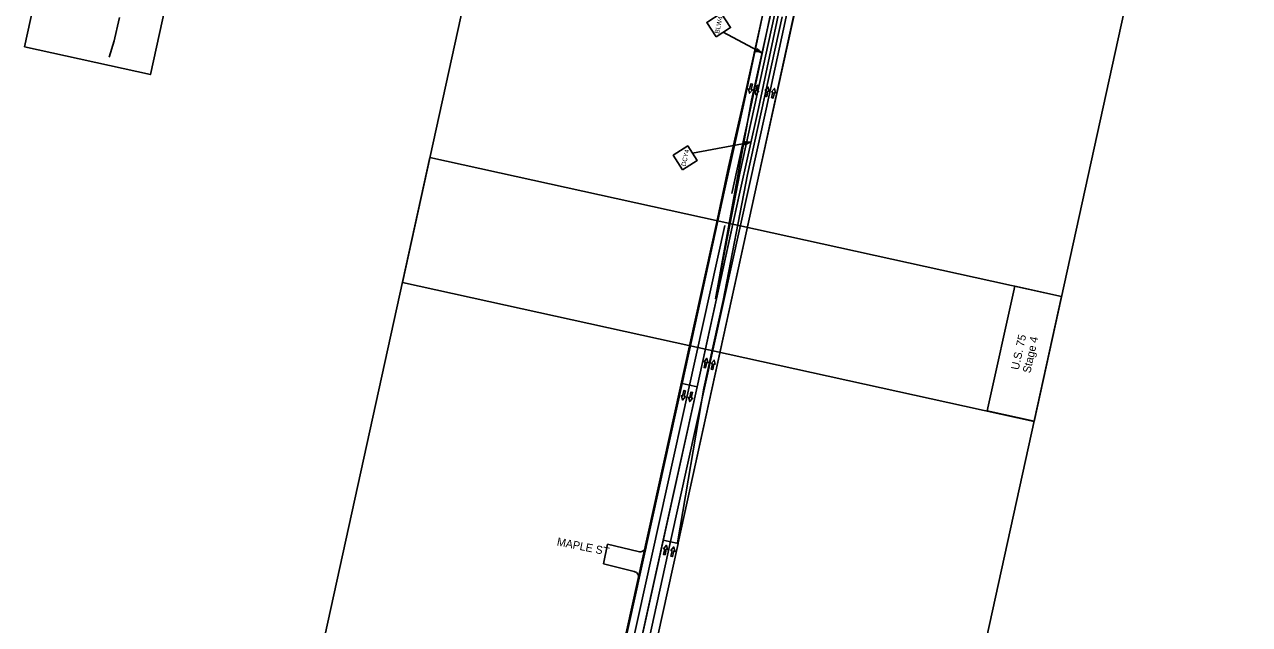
# Model space of a CAD drawing. Extents: x 14104283 to 14120882, y 8635219 to 8671666.
# Drawn here: x 14106628 to 14108541, y 8638109 to 8639045 of the extents above; entities that cross this region are included whole.
import ezdxf

# ---------------------------------------------------------------- set-up
doc = ezdxf.new("R2010")
doc.units = 0
for name, color, linetype in [('Cell', 7, 'Continuous'), ('dsnNonPlotable', 7, 'Continuous'), ('dsnPaintExistingBrokenLaneLineWhite', 7, 'Continuous'), ('dsnPaintExistingDoubleCenterLineYellow', 7, 'Continuous'), ('dsnPaintExistingDoubleCenterYellow', 7, 'Continuous'), ('dsnPaintExistingEdgeLineRightWhite', 7, 'Continuous'), ('dsnPaintPlaceBrokenLaneWhite', 7, 'Continuous'), ('dsnPaintPlaceDoubleCenterLineYellow', 7, 'Continuous'), ('dsnPaintPlaceEdgeLineRightWhite', 7, 'Continuous'), ('dsnPaintRemoveDoubleCenterLineYellow', 7, 'Continuous'), ('dsnPaintRemoveEdgeLineWhite', 7, 'Continuous'), ('dsnPaintRemoveEdgeLineYellow', 7, 'Continuous'), ('dsnShadingPaved', 7, 'Continuous'), ('dsnStdLabel', 7, 'Continuous'), ('dsnTapeRemoveChannelizingWhite', 7, 'Continuous'), ('dsnTapeRemoveChannelizingYellow', 7, 'Continuous'), ('dsnTextFinalPlan', 7, 'Continuous'), ('dsnTextOverlapEven', 7, 'Continuous'), ('dsnTextOverlapOdd', 7, 'Continuous'), ('Terrain', 7, 'Continuous')]:
    doc.layers.add(name, color=color, linetype=linetype)

msp = doc.modelspace()

# ---------------------------------------------------------------- linework, layer by layer
at = {"layer": 'Cell'}
for points in [[(14107762.5, 8638952.7), (14107764.9, 8638952.2), (14107763.1, 8638943.7), (14107764.9, 8638943.3), (14107760.5, 8638937.8), (14107758.8, 8638944.6), (14107760.6, 8638944.2)], [(14107772.5, 8638950.2), (14107774.9, 8638949.6), (14107773.1, 8638941.1), (14107774.9, 8638940.7), (14107770.5, 8638935.2), (14107768.8, 8638942), (14107770.6, 8638941.6)], [(14107787.3, 8638932.7), (14107784.8, 8638933.2), (14107786.7, 8638941.8), (14107784.9, 8638942.2), (14107789.3, 8638947.6), (14107791, 8638940.8), (14107789.2, 8638941.2)], [(14107797.4, 8638930.4), (14107795, 8638931), (14107796.8, 8638939.5), (14107795, 8638939.9), (14107799.4, 8638945.3), (14107801.1, 8638938.6), (14107799.3, 8638939)], [(14107691.9, 8638509.4), (14107689.4, 8638509.9), (14107691.3, 8638518.4), (14107689.5, 8638518.8), (14107693.9, 8638524.3), (14107695.6, 8638517.5), (14107693.7, 8638517.9)], [(14107703, 8638506.7), (14107700.6, 8638507.3), (14107702.5, 8638515.8), (14107700.6, 8638516.2), (14107705, 8638521.6), (14107706.7, 8638514.9), (14107704.9, 8638515.3)], [(14107657.9, 8638474.1), (14107660.4, 8638473.5), (14107658.5, 8638465), (14107660.3, 8638464.6), (14107655.9, 8638459.1), (14107654.2, 8638465.9), (14107656, 8638465.5)], [(14107669, 8638471.6), (14107671.4, 8638471.1), (14107669.5, 8638462.5), (14107671.4, 8638462.1), (14107667, 8638456.7), (14107665.3, 8638463.5), (14107667.1, 8638463.1)], [(14107628.6, 8638217.8), (14107626.1, 8638218.3), (14107628, 8638226.8), (14107626.2, 8638227.2), (14107630.6, 8638232.7), (14107632.3, 8638225.9), (14107630.4, 8638226.3)], [(14107640.2, 8638214.9), (14107637.8, 8638215.5), (14107639.6, 8638224), (14107637.8, 8638224.4), (14107642.2, 8638229.9), (14107643.9, 8638223.1), (14107642.1, 8638223.5)]]:
    msp.add_lwpolyline(points, close=True, dxfattribs=at)
for points in [[(14107760.6, 8638944.2), (14107758.8, 8638944.6), (14107760.5, 8638937.8), (14107764.9, 8638943.3), (14107763.1, 8638943.7), (14107764.9, 8638952.2), (14107762.5, 8638952.7), (14107760.6, 8638944.2)], [(14107770.6, 8638941.6), (14107768.8, 8638942), (14107770.5, 8638935.2), (14107774.9, 8638940.7), (14107773.1, 8638941.1), (14107774.9, 8638949.6), (14107772.5, 8638950.2), (14107770.6, 8638941.6)], [(14107789.2, 8638941.2), (14107791, 8638940.8), (14107789.3, 8638947.6), (14107784.9, 8638942.2), (14107786.7, 8638941.8), (14107784.8, 8638933.2), (14107787.3, 8638932.7), (14107789.2, 8638941.2)], [(14107799.3, 8638939), (14107801.1, 8638938.6), (14107799.4, 8638945.3), (14107795, 8638939.9), (14107796.8, 8638939.5), (14107795, 8638931), (14107797.4, 8638930.4), (14107799.3, 8638939)], [(14107693.7, 8638517.9), (14107695.6, 8638517.5), (14107693.9, 8638524.3), (14107689.5, 8638518.8), (14107691.3, 8638518.4), (14107689.4, 8638509.9), (14107691.9, 8638509.4), (14107693.7, 8638517.9)], [(14107704.9, 8638515.3), (14107706.7, 8638514.9), (14107705, 8638521.6), (14107700.6, 8638516.2), (14107702.5, 8638515.8), (14107700.6, 8638507.3), (14107703, 8638506.7), (14107704.9, 8638515.3)], [(14107656, 8638465.5), (14107654.2, 8638465.9), (14107655.9, 8638459.1), (14107660.3, 8638464.6), (14107658.5, 8638465), (14107660.4, 8638473.5), (14107657.9, 8638474.1), (14107656, 8638465.5)], [(14107667.1, 8638463.1), (14107665.3, 8638463.5), (14107667, 8638456.7), (14107671.4, 8638462.1), (14107669.5, 8638462.5), (14107671.4, 8638471.1), (14107669, 8638471.6), (14107667.1, 8638463.1)], [(14107630.4, 8638226.3), (14107632.3, 8638225.9), (14107630.6, 8638232.7), (14107626.2, 8638227.2), (14107628, 8638226.8), (14107626.1, 8638218.3), (14107628.6, 8638217.8), (14107630.4, 8638226.3)], [(14107642.1, 8638223.5), (14107643.9, 8638223.1), (14107642.2, 8638229.9), (14107637.8, 8638224.4), (14107639.6, 8638224), (14107637.8, 8638215.5), (14107640.2, 8638214.9), (14107642.1, 8638223.5)]]:
    msp.add_lwpolyline(points, dxfattribs=at)
at = {"layer": 'dsnNonPlotable'}
for points in [[(14107218.4, 8638642.3), (14107554.8, 8640173.3), (14108541.3, 8639956.6), (14108204.9, 8638425.6)], [(14106925, 8637306.7), (14107261.4, 8638837.7), (14108247.8, 8638620.9), (14107911.4, 8637089.9)]]:
    msp.add_lwpolyline(points, close=True, dxfattribs=at)
at = {"layer": 'dsnPaintExistingBrokenLaneLineWhite'}
for p, q in [((14107637.1, 8638238.2), (14107786.4, 8638912.8)), ((14107381.2, 8637189.3), (14107721.8, 8638731.5)), ((14107447.5, 8637375), (14107637.1, 8638238.2))]:
    msp.add_line(p, q, dxfattribs=at)
at = {"layer": 'dsnPaintExistingDoubleCenterLineYellow'}
msp.add_line((14107678.5, 8638480), (14107708.8, 8638616.9), dxfattribs=at)
at = {"layer": 'dsnPaintExistingDoubleCenterYellow'}
msp.add_line((14107435.8, 8637377.6), (14107678.5, 8638480), dxfattribs=at)
at = {"layer": 'dsnPaintExistingEdgeLineRightWhite'}
for p, q in [((14107781.7, 8639064), (14107752, 8638929.7)), ((14107648.9, 8638236.1), (14107772.9, 8638800.5)), ((14107708.9, 8638734.4), (14107415.9, 8637407.6))]:
    msp.add_line(p, q, dxfattribs=at)
msp.add_lwpolyline([(14107752, 8638929.7), (14107727.7, 8638822.9), (14107708.9, 8638734.4)], dxfattribs=at)
at = {"layer": 'dsnPaintPlaceBrokenLaneWhite'}
for p, q in [((14107786.4, 8638912.8), (14107843.6, 8639178.3)), ((14107762.7, 8638916.7), (14107793.4, 8639061.3)), ((14107732.8, 8638781.2), (14107762.7, 8638916.8))]:
    msp.add_line(p, q, dxfattribs=at)
at = {"layer": 'dsnPaintPlaceDoubleCenterLineYellow'}
for p, q in [((14107774.4, 8638914.2), (14107805.1, 8639058.9)), ((14107744.5, 8638778.6), (14107774.4, 8638914.2)), ((14107708.8, 8638616.9), (14107744.5, 8638778.6))]:
    msp.add_line(p, q, dxfattribs=at)
at = {"layer": 'dsnPaintPlaceEdgeLineRightWhite'}
msp.add_line((14107772.9, 8638800.5), (14107896.3, 8639362.1), dxfattribs=at)
at = {"layer": 'dsnPaintRemoveDoubleCenterLineYellow'}
msp.add_line((14107796.1, 8639073.9), (14107763.7, 8638927), dxfattribs=at)
at = {"layer": 'dsnPaintRemoveEdgeLineWhite'}
for p, q in [((14107757.1, 8638810.8), (14107811.2, 8639057.1)), ((14107689.3, 8638477.5), (14107719.5, 8638614.2))]:
    msp.add_line(p, q, dxfattribs=at)
at = {"layer": 'dsnPaintRemoveEdgeLineYellow'}
msp.add_line((14107745.3, 8638813.2), (14107799.4, 8639059.7), dxfattribs=at)
at = {"layer": 'dsnShadingPaved'}
for p, q in [((14107751, 8638919.2), (14107781.7, 8639063.9)), ((14107805.1, 8639058.9), (14107774.4, 8638914.2)), ((14107721, 8638783.8), (14107751, 8638919.4)), ((14107774.4, 8638914.2), (14107744.5, 8638778.6)), ((14107685.3, 8638622.1), (14107721, 8638783.8)), ((14107744.5, 8638778.6), (14107708.8, 8638616.9)), ((14107655.1, 8638485.2), (14107685.3, 8638622.1)), ((14107708.8, 8638616.9), (14107678.5, 8638480)), ((14107678.5, 8638480), (14107655.1, 8638485.2)), ((14107532.2, 8638203.4), (14107538.8, 8638234.3)), ((14107538.8, 8638234.3), (14107586.6, 8638222.6)), ((14107598.8, 8638230.1), (14107587.6, 8638179.7)), ((14107580.3, 8638191.6), (14107532.2, 8638203.4))]:
    msp.add_line(p, q, dxfattribs=at)
for points in [[(14107649.1, 8638235.5), (14107625.7, 8638240.7), (14107678.5, 8638480), (14107744.5, 8638778.6), (14107774.4, 8638914.2), (14107805.1, 8639058.9), (14107831.9, 8639180.9), (14107855.4, 8639175.7), (14107834.6, 8639081.3), (14107772.9, 8638800.5), (14107710.9, 8638518.3), (14107648.9, 8638236.1)], [(14107392.9, 8637186.7), (14107369.5, 8637191.9), (14107655.1, 8638485.1), (14107678.5, 8638480)], [(14107416.4, 8637181.6), (14107649.1, 8638235.5), (14107625.7, 8638240.7), (14107392.9, 8637186.7)]]:
    msp.add_lwpolyline(points, close=True, dxfattribs=at)
for centre, start, end in [((14107589, 8638232.3), 256.2115, 347.5463), ((14107577.9, 8638181.9), 347.5463, 76.2115)]:
    msp.add_arc(centre, 10, start, end, dxfattribs=at)
at = {"layer": 'dsnStdLabel'}
for p, q in [((14107719.5, 8639033), (14107780.7, 8639000.2)), ((14107671.3, 8638844.3), (14107763.6, 8638861.7))]:
    msp.add_line(p, q, dxfattribs=at)
for points in [[(14107708.1, 8639025.7), (14107730.9, 8639040.3), (14107716.3, 8639063), (14107693.6, 8639048.4)], [(14107655.9, 8638818.4), (14107678.6, 8638832.9), (14107664.1, 8638855.7), (14107641.3, 8638841.1)]]:
    msp.add_lwpolyline(points, close=True, dxfattribs=at)
for centre, radius, start, end in [((14107763.8, 8639009.3), 8.86, 314.1068, 349.5752), ((14107769.9, 8638980), 22.9, 61.8409, 89.9122), ((14107791.6, 8639020.4), 22.9, 213.7698, 241.8411), ((14107759.4, 8638884.2), 22.9, 252.5977, 280.669), ((14107744.7, 8638858.1), 8.86, 352.9347, 28.4031), ((14107767.9, 8638839.1), 22.9, 100.6688, 128.7401)]:
    msp.add_arc(centre, radius, start, end, dxfattribs=at)
at = {"layer": 'dsnTapeRemoveChannelizingWhite'}
for p, q in [((14107719.5, 8638614.2), (14107757.1, 8638810.8)), ((14107648.2, 8638236.2), (14107689.3, 8638477.5))]:
    msp.add_line(p, q, dxfattribs=at)
at = {"layer": 'dsnTapeRemoveChannelizingYellow'}
for p in [(14107763.7, 8638927), (14107745.3, 8638813.2)]:
    msp.add_line(p, (14107707.5, 8638617.1), dxfattribs=at)
at = {"layer": 'dsnTextFinalPlan'}
msp.add_lwpolyline([(14106628.1, 8639010.3), (14106841.8, 8639982.7), (14107038.6, 8639939.4), (14106824.9, 8638967)], close=True, dxfattribs=at)
at = {"layer": 'dsnTextOverlapEven'}
msp.add_lwpolyline([(14106628.1, 8639010.3), (14106841.8, 8639982.7), (14107038.6, 8639939.4), (14106824.9, 8638967)], close=True, dxfattribs=at)
at = {"layer": 'dsnTextOverlapOdd'}
for points in [[(14108247.8, 8638620.9), (14108205.1, 8638426.3), (14108131.8, 8638442.4), (14108174.6, 8638637)], [(14108131.8, 8638442.4), (14108174.6, 8638637), (14108247.8, 8638620.9), (14108205.1, 8638426.3)]]:
    msp.add_lwpolyline(points, close=True, dxfattribs=at)
at = {"layer": 'Terrain'}
msp.add_lwpolyline([(14106760.5, 8638994.3), (14106768, 8639019.7), (14106769.4, 8639024.1), (14106775, 8639049.3), (14106776.4, 8639055.8)], dxfattribs=at)

# ---------------------------------------------------------------- texts
at = {"layer": 'dsnStdLabel'}
for s, p in [('BLW4', (14107712.8, 8639030.4)), ('DCY4', (14107660.7, 8638823.4))]:
    msp.add_text(s, height=7.2, rotation=77.6078, dxfattribs=at).set_placement(p)
at = {"layer": 'dsnTextOverlapOdd'}
for s, rotation, p in [('U.S. 75', 77.6078, (14108180.8, 8638505.4)), ('Stage 4', 77.6078, (14108199, 8638500.4)), ('MAPLE ST', 348.6912, (14107458.9, 8638232.5))]:
    msp.add_text(s, height=12.5, rotation=rotation, dxfattribs=at).set_placement(p)

doc.saveas('drawing.dxf')
